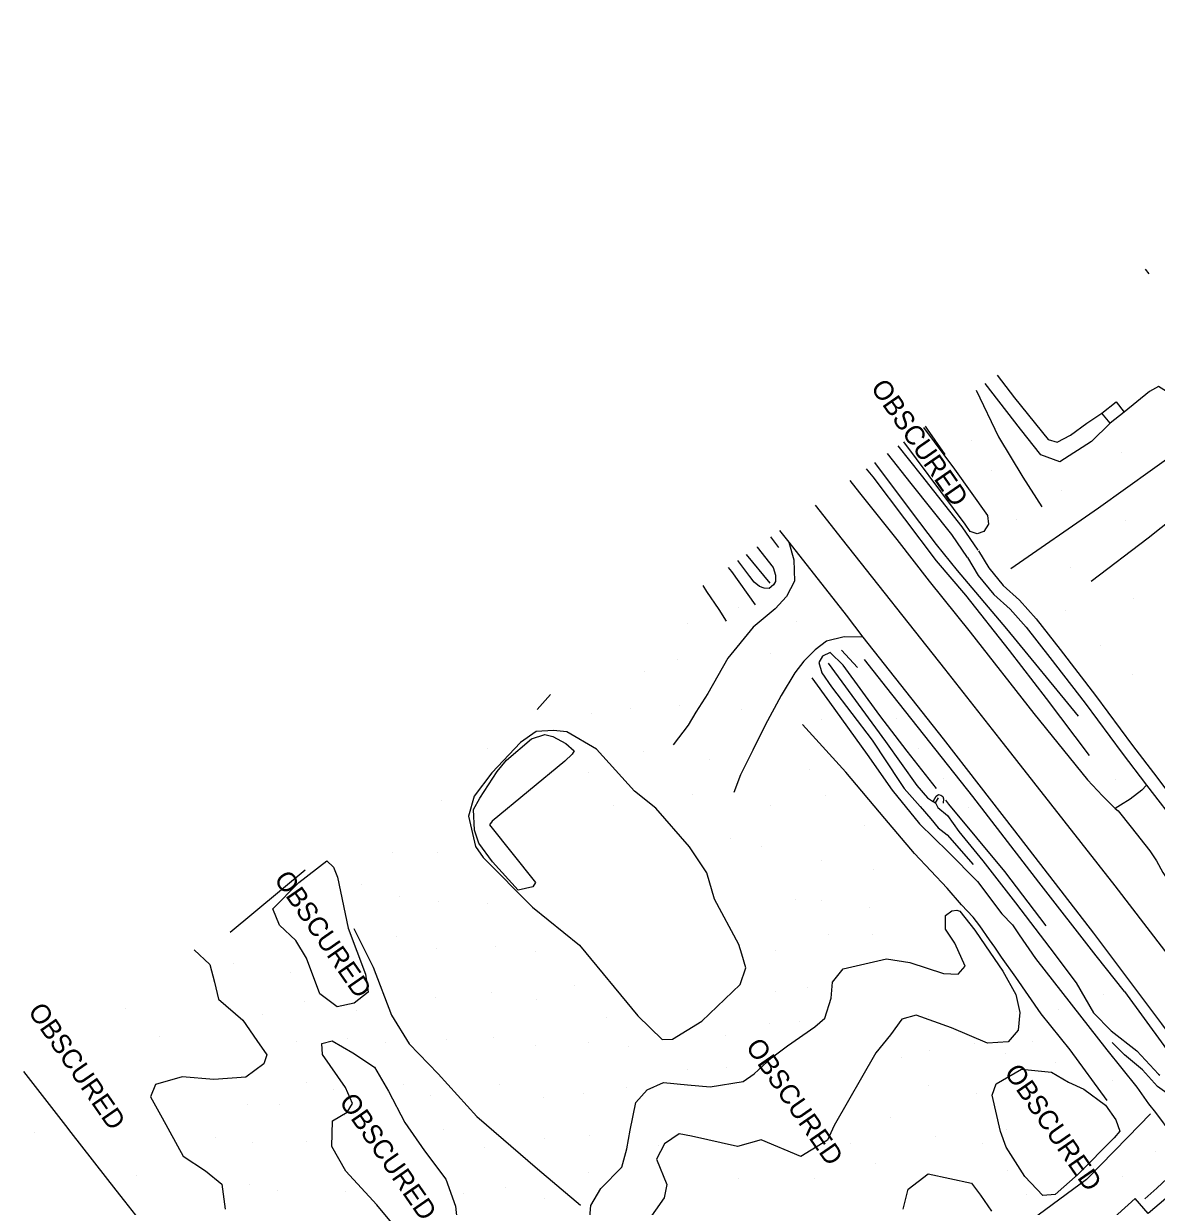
# Model space of a CAD drawing. Extents: x 1497074 to 1501343, y 481943 to 486114.
# Drawn here: x 1497074.4 to 1497425.4, y 484246.4 to 484612.8 of the extents above; entities that cross this region are included whole.
import ezdxf

# ---------------------------------------------------------------- set-up
doc = ezdxf.new("R2010")
doc.units = 0
for name, color, linetype in [('PH Exist DTM Boundary', 7, 'Continuous'), ('PH Exist DTM Breakline', 7, 'Continuous'), ('PH Exist DTM Obscure Area', 7, 'Continuous'), ('PH Exist DTM Obscure Area Text', 7, 'Continuous'), ('PH Exist DTM Point', 7, 'Continuous')]:
    doc.layers.add(name, color=color, linetype=linetype)

msp = doc.modelspace()

# ---------------------------------------------------------------- linework, layer by layer
at = {"layer": 'PH Exist DTM Boundary'}
msp.add_lwpolyline([(1497074.44, 484288.18), (1497081.61, 484278.97), (1497087.44, 484271.49), (1497089.09, 484269.37), (1497103.01, 484251.49), (1497105.67, 484248.08), (1497109.09, 484243.69)], dxfattribs=at)
at = {"layer": 'PH Exist DTM Breakline'}
for points in [[(1497380.31, 484444.03), (1497407.46, 484462.86), (1497432.52, 484480.83), (1497445.3, 484492.35), (1497449.21, 484495.11), (1497452.97, 484497.84), (1497467.42, 484507.84), (1497481.71, 484518.61), (1497492.98, 484526.47), (1497505.2, 484533.04), (1497524.07, 484543.21), (1497536.14, 484549.91), (1497550.63, 484561.75), (1497563.67, 484572.64), (1497570.03, 484578.99), (1497584.26, 484591.02), (1497594.69, 484603.43), (1497601.55, 484612.82)], [(1497438, 484548.3), (1497438.75, 484547.82), (1497448.29, 484535.66), (1497455.84, 484525.45), (1497458.93, 484520.6), (1497459.34, 484517.68), (1497458.41, 484515.46), (1497457.51, 484514.05), (1497455.73, 484512.21), (1497450.73, 484508.04), (1497439.58, 484500.2), (1497433.19, 484496.82), (1497431.49, 484497.08), (1497429.37, 484498.31), (1497426.06, 484500.42), (1497423.32, 484498.86), (1497415.42, 484492.49)], [(1497421.95, 484536.81), (1497423.12, 484535.31)], [(1497376.03, 484503.96), (1497381.48, 484496.95), (1497391.87, 484483.98), (1497394.7, 484483.15), (1497398.75, 484485.34), (1497403.84, 484489.05), (1497408.55, 484492.15)], [(1497369.53, 484499.3), (1497376.5, 484484.83), (1497384.02, 484472.34), (1497389.92, 484463.16)], [(1497411.07, 484489.01), (1497405.35, 484483.38), (1497395.46, 484477.08), (1497389.56, 484479.23), (1497383.26, 484487.24), (1497372.34, 484501.31)], [(1497359.98, 484479.34), (1497354.51, 484487.22), (1497353.89, 484488.12)], [(1497370.19, 484449.68), (1497365.23, 484456.95), (1497352.62, 484472.9), (1497345.4, 484482.04)], [(1497459.96, 484480.9), (1497452.74, 484475.46), (1497443.07, 484468.33), (1497434.38, 484462.64), (1497422.88, 484453.47), (1497405.16, 484440.04)], [(1497338.11, 484476.83), (1497349.44, 484461.65), (1497357.19, 484451.49), (1497363.67, 484443.43)], [(1497366.88, 484447.43), (1497362, 484454.58), (1497349.48, 484470.42), (1497342.14, 484479.71)], [(1497335.46, 484474.93), (1497337.56, 484472.39), (1497357.16, 484446.42), (1497366.26, 484435.81), (1497379.79, 484418.68), (1497391.25, 484403.79), (1497404.56, 484386.16)], [(1497330.44, 484471.34), (1497333.46, 484467.48), (1497345.01, 484453.04), (1497354.97, 484440.14), (1497367.71, 484424.32), (1497387.46, 484399.15), (1497404.03, 484378.57), (1497408.73, 484373.66), (1497412.66, 484369.74), (1497413.55, 484368.93), (1497417.57, 484363.9), (1497423.33, 484356.54), (1497425.41, 484353.48), (1497427.36, 484349.84), (1497429.67, 484346.47), (1497444.52, 484327.11), (1497463.32, 484303.15), (1497468.81, 484296.48), (1497474.96, 484288.97)], [(1497319.69, 484463.65), (1497328.05, 484453.07), (1497359.79, 484412.96), (1497376.84, 484391.29), (1497412.52, 484345.72), (1497442.28, 484307.03), (1497466.31, 484275.69)], [(1497308.67, 484455.76), (1497311.49, 484452.19), (1497329.26, 484429.59), (1497334.45, 484422.8), (1497359.39, 484391.31), (1497381.45, 484362.8), (1497405.91, 484331.07), (1497427.04, 484302.98), (1497436.32, 484290.36), (1497440.65, 484284.44), (1497450.41, 484270.3), (1497454.94, 484263.4), (1497457.72, 484259.47)], [(1497311.49, 484452.19), (1497313.11, 484446.69), (1497313.27, 484440.11), (1497310.79, 484435.32), (1497307.34, 484431.5), (1497300.5, 484425.82), (1497292.63, 484416.24), (1497286.44, 484405.29), (1497282.74, 484399.54), (1497280.31, 484395.55), (1497275.69, 484389.4)], [(1497301.67, 484450.75), (1497301.71, 484450.69), (1497306.66, 484444.35), (1497307.42, 484441.93), (1497307.41, 484440.06), (1497306.79, 484438.95), (1497305.41, 484437.86), (1497303.92, 484437.97), (1497302.45, 484438.42), (1497300.74, 484439.78), (1497299.45, 484441.54), (1497295.71, 484446.49)], [(1497308.41, 484450.52), (1497305.95, 484453.81)], [(1497298.29, 484448.34), (1497305.65, 484439.5)], [(1497366.88, 484447.43), (1497370.22, 484441.91), (1497375.02, 484436.01), (1497380.1, 484431.39), (1497385.1, 484425.83), (1497392.37, 484416.49), (1497403.31, 484402.29), (1497414.81, 484386.8), (1497422.32, 484376.95), (1497432.53, 484363.66), (1497446.51, 484345.69), (1497462.67, 484324.82), (1497475.68, 484307.87), (1497480.66, 484301.39)], [(1497370.34, 484449.52), (1497373.53, 484444.24), (1497377.96, 484438.8), (1497382.96, 484434.25), (1497388.21, 484428.42), (1497395.56, 484418.96), (1497406.54, 484404.72), (1497418.04, 484389.23), (1497425.53, 484379.39), (1497435.95, 484365.36), (1497449.43, 484347.99), (1497465.43, 484326.98), (1497478.45, 484310.03), (1497483.42, 484303.54)], [(1497292.68, 484444.32), (1497293.72, 484443.07), (1497301.14, 484432.81)], [(1497363.67, 484443.43), (1497378.92, 484425.34), (1497401.22, 484398.28)], [(1497292.19, 484427.7), (1497289.98, 484431.31), (1497286.11, 484436.89), (1497284.96, 484438.8)], [(1497334.45, 484422.8), (1497328.72, 484422.86), (1497323.19, 484421.51), (1497319.67, 484418.83), (1497316.15, 484415.31), (1497313.36, 484411.69), (1497309.19, 484404.7), (1497304.2, 484395.47), (1497300.37, 484387.72), (1497296.56, 484380.11), (1497294.45, 484374.6)], [(1497357.32, 484375.84), (1497348.16, 484387.45), (1497339.71, 484398.51), (1497328.35, 484414.13), (1497324.36, 484418.03), (1497321.98, 484416.9), (1497320.81, 484414.94), (1497321.78, 484411.68), (1497324.74, 484407.42), (1497337.3, 484390.81), (1497346.06, 484377.7), (1497347.31, 484375.89), (1497352.26, 484370.26), (1497355.5, 484366.44), (1497357.79, 484363.68), (1497360.56, 484361.49), (1497368.62, 484352.39)], [(1497332.81, 484413.39), (1497327.83, 484418.72)], [(1497323.75, 484414.71), (1497341.44, 484390.4), (1497351.23, 484376.81), (1497354.44, 484373.01), (1497355.76, 484372.13), (1497356.92, 484371.45), (1497357.93, 484373.04)], [(1497415.53, 484312.97), (1497406.7, 484324.01), (1497388.95, 484346.82), (1497368.49, 484373.38), (1497341.91, 484407.02), (1497334.95, 484415.86)], [(1497318.7, 484410.14), (1497324.17, 484402.6), (1497335.82, 484386.46), (1497343.54, 484375.32), (1497351.99, 484364.9), (1497360.88, 484356.29), (1497369.94, 484347.03), (1497377.57, 484337.11), (1497380.78, 484333.64), (1497382.92, 484330.54), (1497387.98, 484323.24), (1497399, 484309.04), (1497410.01, 484294.98), (1497419.33, 484283.35), (1497422.99, 484278.22), (1497425.15, 484275.56), (1497430.19, 484268.72), (1497432.99, 484262.82), (1497431.99, 484258.09), (1497425.55, 484252.06), (1497421.88, 484248.73)], [(1497237.72, 484405), (1497233.59, 484400.32)], [(1497410.21, 484279.26), (1497398.74, 484294.92), (1497389.71, 484306.09), (1497381.84, 484317.41), (1497377.46, 484323.64), (1497375.32, 484326.71), (1497373.71, 484329.02), (1497370.74, 484333.31), (1497368.67, 484336.03), (1497365.07, 484339.87), (1497360.59, 484344.98), (1497350.43, 484355.78), (1497341.26, 484366.56), (1497329.21, 484380.93), (1497315.74, 484395.74)], [(1497216.86, 484354.5), (1497232.08, 484339.16), (1497246.69, 484327.36), (1497264.71, 484305.43), (1497272.29, 484298.14), (1497275.5, 484298.26), (1497284.61, 484303.85), (1497296.49, 484315.21), (1497298.22, 484320.32), (1497297.01, 484324.56), (1497295.99, 484327.53), (1497288.48, 484341.58), (1497286.07, 484349.75), (1497280.79, 484357.86), (1497270.35, 484369.83), (1497263.7, 484375.04), (1497251.98, 484388.12), (1497242.78, 484393.39), (1497238.65, 484393.85), (1497233.26, 484393.53), (1497228.36, 484390.13), (1497219.48, 484380.73), (1497214.04, 484373.47), (1497212.26, 484367.35), (1497214.44, 484357.93), (1497216.86, 484354.5)], [(1497356.38, 484372.07), (1497357.13, 484373.49), (1497357.88, 484374.01), (1497358.65, 484373.86), (1497359.22, 484373.4), (1497359.47, 484372.72), (1497359.31, 484371.34)], [(1497422.32, 484376.95), (1497420.88, 484375.35), (1497417.3, 484372.6), (1497414.29, 484370.76), (1497412.66, 484369.74)], [(1497356.92, 484371.45), (1497357.69, 484369.97), (1497360.64, 484367.48), (1497364.24, 484362.52), (1497371.62, 484353.47), (1497381.8, 484340.49), (1497392.43, 484326.53), (1497400.51, 484315.72), (1497405.89, 484306.36), (1497411.39, 484300.86), (1497419.39, 484294.64), (1497426.06, 484287.43), (1497426.46, 484287.07)], [(1497391.25, 484333.36), (1497378.41, 484350.19), (1497361.14, 484371), (1497360.22, 484372.31)], [(1497161.69, 484350.6), (1497138.38, 484331.23)], [(1497176.75, 484332.53), (1497182.74, 484320.56), (1497188.44, 484305.7), (1497193.91, 484296.77), (1497202.85, 484287.51), (1497214.84, 484274.29), (1497233.69, 484258.05), (1497246.93, 484246.76)], [(1497415.53, 484312.97), (1497427.72, 484296.3), (1497432.27, 484289.74), (1497435.18, 484284.58), (1497438.53, 484278.12), (1497440.28, 484275.19), (1497441.12, 484274.09)], [(1497432.89, 484276.93), (1497430.47, 484280.16), (1497425.74, 484283.58), (1497421.08, 484288.71), (1497415.48, 484293.34), (1497411.72, 484297.19)], [(1497423.6, 484275.1), (1497416.57, 484267.88), (1497403.75, 484254.79), (1497337.98, 484206.23), (1497311.68, 484180.57)], [(1497437.56, 484251.09), (1497434.71, 484254.45), (1497428.34, 484248.9), (1497422.88, 484244.21), (1497418.82, 484248.83), (1497401.66, 484233.36), (1497383.44, 484217.08), (1497360.56, 484196.64), (1497363.2, 484193.52), (1497365.66, 484190.68)]]:
    msp.add_lwpolyline(points, dxfattribs=at)
msp.add_lwpolyline([(1497415.42, 484492.49), (1497411.07, 484489.01), (1497408.55, 484492.15), (1497412.91, 484495.63)], close=True, dxfattribs=at)
at = {"layer": 'PH Exist DTM Obscure Area'}
for points in [[(1497353.29, 484487.69), (1497362.82, 484474.76), (1497373.13, 484460.42), (1497373.36, 484457.74), (1497371.96, 484455.55), (1497369.88, 484454.74), (1497367.73, 484455.46), (1497366.12, 484457.74), (1497362.58, 484462.67)], [(1497362.58, 484462.67), (1497347.16, 484483.3)], [(1497238.45, 484392.02), (1497242.42, 484389.8), (1497245.03, 484387.58), (1497244.4, 484386.52), (1497242.15, 484384.33), (1497219.63, 484365.76), (1497218.77, 484364.63), (1497233.07, 484346.79), (1497232.22, 484345.38), (1497227.71, 484344.44), (1497219.69, 484353.17), (1497215.51, 484358.98), (1497214.1, 484362.99), (1497213.84, 484369.35), (1497215.79, 484372.87), (1497221.14, 484381.18), (1497224.02, 484384.71), (1497231.79, 484391.3), (1497235.94, 484392.64), (1497238.45, 484392.02)], [(1497171.69, 484348.38), (1497174.99, 484332.6), (1497180.35, 484318.37), (1497181.21, 484312.84), (1497176.88, 484309.34), (1497171.58, 484308.25), (1497166.24, 484312.25), (1497162.13, 484323.35), (1497158.75, 484328.85), (1497153.72, 484333.56), (1497151.64, 484338.66), (1497159.74, 484346.78), (1497168.42, 484353.44), (1497170.43, 484351.53), (1497171.69, 484348.38)], [(1497249.15, 484234.83), (1497250.19, 484246.72), (1497253.26, 484251.94), (1497259.75, 484258.62), (1497261.29, 484264.26), (1497262.35, 484270.07), (1497264.14, 484278.6), (1497267.66, 484282.51), (1497272.71, 484284.83), (1497280.13, 484284.08), (1497287.11, 484283.48), (1497297.42, 484285.07), (1497300.83, 484287.54), (1497306.2, 484292.44), (1497311.14, 484296.2), (1497319.56, 484302.01), (1497322.66, 484304.77), (1497324.68, 484310.95), (1497325.09, 484315.94), (1497328.35, 484320.06), (1497341.76, 484323.13), (1497349, 484321.99), (1497359.49, 484318.61), (1497364.02, 484318.39), (1497366.21, 484320.81), (1497362.97, 484327.94), (1497360.12, 484332.35), (1497360.05, 484336.56), (1497362.06, 484337.96), (1497363.61, 484338.22), (1497364.46, 484337.84)], [(1497364.46, 484337.84), (1497369.16, 484331.98), (1497372.51, 484327.11), (1497377.83, 484319.35), (1497381.87, 484312.04), (1497383.12, 484306.46), (1497382.58, 484300.99), (1497379.49, 484297.36), (1497373.1, 484297), (1497361.93, 484301.74), (1497350.98, 484305.66), (1497346.57, 484304.46), (1497343.04, 484299.58), (1497338.47, 484294), (1497325.53, 484271.5), (1497323.51, 484266.94), (1497315.29, 484261.87), (1497302.99, 484267.01), (1497295.61, 484264.98), (1497281.36, 484268.19), (1497277.53, 484268.93), (1497272.97, 484265.77), (1497270.52, 484261.04), (1497273.77, 484253.24), (1497272.86, 484249.1), (1497267.53, 484241.48)], [(1497127.23, 484325.95), (1497132.11, 484321.35), (1497133.56, 484315.9), (1497134.79, 484310.64), (1497142.31, 484304.15), (1497146.7, 484297.84), (1497149.76, 484293.34), (1497148.84, 484290.56), (1497143.26, 484286.44), (1497133.36, 484285.76), (1497123.53, 484286.57), (1497115.26, 484284.22), (1497113.78, 484280.41), (1497117.41, 484273.84), (1497123.9, 484262), (1497130.79, 484257.42), (1497135.89, 484253.35), (1497136.89, 484245.62)], [(1497198.87, 484235.26), (1497188.98, 484240.77), (1497183.88, 484246.95), (1497174.23, 484257.3), (1497169.92, 484264.98), (1497170.1, 484272.92), (1497174.72, 484275.58), (1497176.34, 484278.28), (1497174.16, 484283.29), (1497166.99, 484293.5), (1497166.79, 484296.87), (1497170.07, 484297.71), (1497176.43, 484293.96), (1497183.18, 484289.56), (1497187.53, 484282.09), (1497192.56, 484272.38), (1497198.64, 484263.69), (1497205.23, 484254.84), (1497208.21, 484246.51), (1497209.21, 484237.61), (1497208.02, 484234.48), (1497204.69, 484233.14), (1497201.39, 484234.11), (1497198.87, 484235.26)], [(1497375.72, 484284.4), (1497383.65, 484288.9), (1497392.91, 484287.96), (1497398.17, 484284.91), (1497402.94, 484282.77), (1497409.6, 484277.79), (1497412.85, 484273.28), (1497414.07, 484269.78), (1497412.36, 484267.62), (1497401.19, 484256.37), (1497394.02, 484250.12), (1497390.2, 484249.85), (1497384.67, 484255.7), (1497378.89, 484264.73), (1497377.16, 484269.66), (1497374.56, 484280.89), (1497375.72, 484284.4)], [(1497346.97, 484245.6), (1497348.49, 484251.78), (1497354.74, 484256.49), (1497368.08, 484253.63), (1497370.93, 484249.88), (1497374.28, 484244.93)]]:
    msp.add_lwpolyline(points, dxfattribs=at)
at = {"layer": 'PH Exist DTM Point'}
for p, q in [((1497368.19, 484483.57), (1497368.19, 484483.57)), ((1497414.72, 484480.11), (1497414.72, 484480.11)), ((1497374.42, 484474.45), (1497374.42, 484474.45)), ((1497395.86, 484468.17), (1497395.86, 484468.17)), ((1497382.14, 484459.25), (1497382.14, 484459.25)), ((1497415.85, 484458.84), (1497415.85, 484458.84)), ((1497398.74, 484444.32), (1497398.74, 484444.32)), ((1497418.36, 484434.79), (1497418.36, 484434.79)), ((1497295.88, 484431.93), (1497295.88, 484431.93)), ((1497397.27, 484430.96), (1497397.27, 484430.96)), ((1497280.18, 484427.14), (1497280.18, 484427.14)), ((1497313.99, 484427.57), (1497313.99, 484427.57)), ((1497408.21, 484420.09), (1497408.21, 484420.09)), ((1497277.15, 484415.95), (1497277.15, 484415.95)), ((1497305.93, 484417.59), (1497305.93, 484417.59)), ((1497266.83, 484411.98), (1497266.83, 484411.98)), ((1497417.97, 484411.07), (1497417.97, 484411.07)), ((1497262.35, 484400.57), (1497262.35, 484400.57)), ((1497277.77, 484401.61), (1497277.77, 484401.61)), ((1497296.91, 484400.48), (1497296.91, 484400.48)), ((1497250.25, 484399.22), (1497250.25, 484399.22)), ((1497321.62, 484397.36), (1497321.62, 484397.36)), ((1497344.93, 484397.53), (1497344.93, 484397.53)), ((1497351.82, 484388.43), (1497351.82, 484388.43)), ((1497218.29, 484388.35), (1497218.29, 484388.35)), ((1497266.61, 484387.49), (1497266.61, 484387.49)), ((1497287.08, 484384.88), (1497287.08, 484384.88)), ((1497317.9, 484381.62), (1497317.9, 484381.62)), ((1497249.42, 484380.92), (1497249.42, 484380.92)), ((1497359.51, 484378.85), (1497359.51, 484378.85)), ((1497412.7, 484378.56), (1497412.7, 484378.56)), ((1497281.67, 484373.93), (1497281.67, 484373.93)), ((1497322.91, 484373.86), (1497322.91, 484373.86)), ((1497203.79, 484372.04), (1497203.79, 484372.04)), ((1497257.07, 484370.55), (1497257.07, 484370.55)), ((1497305.92, 484370.63), (1497305.92, 484370.63)), ((1497367.11, 484370.04), (1497367.11, 484370.04)), ((1497334.95, 484364.3), (1497334.95, 484364.3)), ((1497293.51, 484360.27), (1497293.51, 484360.27)), ((1497188.65, 484356.07), (1497188.65, 484356.07)), ((1497202.65, 484356.01), (1497202.65, 484356.01)), ((1497302.97, 484357.86), (1497302.97, 484357.86)), ((1497321.69, 484353.53), (1497321.69, 484353.53)), ((1497337.63, 484350.92), (1497337.63, 484350.92)), ((1497179.06, 484346.05), (1497179.06, 484346.05)), ((1497190.91, 484342.34), (1497190.91, 484342.34)), ((1497313.68, 484341.6), (1497313.68, 484341.6)), ((1497321.68, 484341.28), (1497321.68, 484341.28)), ((1497203.05, 484340.74), (1497203.05, 484340.74)), ((1497218.15, 484340.23), (1497218.15, 484340.23)), ((1497336.62, 484339.05), (1497336.62, 484339.05)), ((1497190.01, 484329.94), (1497190.01, 484329.94)), ((1497323.76, 484330.75), (1497323.76, 484330.75)), ((1497337.48, 484330.74), (1497337.48, 484330.74)), ((1497202.39, 484326.45), (1497202.39, 484326.45)), ((1497220.53, 484326.83), (1497220.53, 484326.83)), ((1497233.13, 484325.53), (1497233.13, 484325.53)), ((1497307.37, 484325.65), (1497307.37, 484325.65)), ((1497139.52, 484321.75), (1497139.52, 484321.75)), ((1497157.15, 484318.9), (1497157.15, 484318.9)), ((1497219.36, 484312.77), (1497219.36, 484312.77)), ((1497245.21, 484314.78), (1497245.21, 484314.78)), ((1497307.4, 484312.91), (1497307.4, 484312.91)), ((1497317.26, 484314.28), (1497317.26, 484314.28)), ((1497409, 484312.16), (1497409, 484312.16)), ((1497161.42, 484309.83), (1497161.42, 484309.83)), ((1497202.14, 484310.99), (1497202.14, 484310.99)), ((1497233.43, 484310.48), (1497233.43, 484310.48)), ((1497106.12, 484307.7), (1497106.12, 484307.7)), ((1497148.42, 484305.99), (1497148.42, 484305.99)), ((1497177.52, 484307.2), (1497177.52, 484307.2)), ((1497254.97, 484305.09), (1497254.97, 484305.09)), ((1497354.89, 484305.21), (1497354.89, 484305.21)), ((1497381.93, 484306.7), (1497381.93, 484306.7)), ((1497395.03, 484307.31), (1497395.03, 484307.31)), ((1497305.46, 484303.04), (1497305.46, 484303.04)), ((1497314.94, 484303.85), (1497314.94, 484303.85)), ((1497116.4, 484299.06), (1497116.4, 484299.06)), ((1497158.86, 484297.39), (1497158.86, 484297.39)), ((1497174.92, 484298.38), (1497174.92, 484298.38)), ((1497186.47, 484297.05), (1497186.47, 484297.05)), ((1497205.36, 484298.03), (1497205.36, 484298.03)), ((1497219.95, 484298.61), (1497219.95, 484298.61)), ((1497249.52, 484297.13), (1497249.52, 484297.13)), ((1497291.8, 484299.36), (1497291.8, 484299.36)), ((1497369.19, 484297), (1497369.19, 484297)), ((1497386.96, 484297.54), (1497386.96, 484297.54)), ((1497233.16, 484296.22), (1497233.16, 484296.22)), ((1497261.99, 484296.04), (1497261.99, 484296.04)), ((1497355.24, 484294.66), (1497355.24, 484294.66)), ((1497378.71, 484293.68), (1497378.71, 484293.68)), ((1497292.19, 484289.59), (1497292.19, 484289.59)), ((1497346.49, 484292.6), (1497346.49, 484292.6)), ((1497394.25, 484290.88), (1497394.25, 484290.88)), ((1497280.06, 484288.7), (1497280.06, 484288.7)), ((1497161.94, 484284.71), (1497161.94, 484284.71)), ((1497170.57, 484282.69), (1497170.57, 484282.69)), ((1497192.17, 484284.23), (1497192.17, 484284.23)), ((1497221.96, 484284.25), (1497221.96, 484284.25)), ((1497261.29, 484283.36), (1497261.29, 484283.36)), ((1497354.85, 484283.93), (1497354.85, 484283.93)), ((1497411.92, 484285.48), (1497411.92, 484285.48)), ((1497200.63, 484280.89), (1497200.63, 484280.89)), ((1497235.59, 484280.16), (1497235.59, 484280.16)), ((1497248.05, 484281.45), (1497248.05, 484281.45)), ((1497369.67, 484281.25), (1497369.67, 484281.25)), ((1497143.72, 484278.03), (1497143.72, 484278.03)), ((1497153.75, 484277.86), (1497153.75, 484277.86)), ((1497173.97, 484274.66), (1497173.97, 484274.66)), ((1497343.13, 484273.82), (1497343.13, 484273.82)), ((1497077.9, 484269.28), (1497077.9, 484269.28)), ((1497133.73, 484267.71), (1497133.73, 484267.71)), ((1497204.68, 484270.15), (1497204.68, 484270.15)), ((1497249.67, 484268.29), (1497249.67, 484268.29)), ((1497262.08, 484269.58), (1497262.08, 484269.58)), ((1497357.09, 484268.22), (1497357.09, 484268.22)), ((1497379.07, 484270.38), (1497379.07, 484270.38)), ((1497145.38, 484266.37), (1497145.38, 484266.37)), ((1497162.14, 484266.67), (1497162.14, 484266.67)), ((1497217.23, 484264.55), (1497217.23, 484264.55)), ((1497235.81, 484267.41), (1497235.81, 484267.41)), ((1497271.25, 484265.34), (1497271.25, 484265.34)), ((1497330.55, 484266.01), (1497330.55, 484266.01)), ((1497371.56, 484265.77), (1497371.56, 484265.77)), ((1497425.08, 484263.44), (1497425.08, 484263.44)), ((1497249.58, 484256.87), (1497249.58, 484256.87)), ((1497259.3, 484258.62), (1497259.3, 484258.62)), ((1497338.3, 484259.83), (1497338.3, 484259.83)), ((1497379.3, 484257.55), (1497379.3, 484257.55)), ((1497109.41, 484255.93), (1497109.41, 484255.93)), ((1497144.38, 484253.14), (1497144.38, 484253.14)), ((1497296.07, 484254.94), (1497296.07, 484254.94)), ((1497319.48, 484255), (1497319.48, 484255)), ((1497414.98, 484255.59), (1497414.98, 484255.59)), ((1497153, 484251.48), (1497153, 484251.48)), ((1497174.05, 484250.95), (1497174.05, 484250.95)), ((1497210.84, 484250.55), (1497210.84, 484250.55)), ((1497223.59, 484252.15), (1497223.59, 484252.15)), ((1497385.18, 484250.08), (1497385.18, 484250.08)), ((1497235.91, 484248.98), (1497235.91, 484248.98))]:
    msp.add_line(p, q, dxfattribs=at)

# ---------------------------------------------------------------- texts
at = {"layer": 'PH Exist DTM Obscure Area Text'}
for p in [(1497336.7, 484500.05), (1497151.83, 484347.8), (1497075.59, 484306.87), (1497297.96, 484295.9), (1497378.09, 484287.93), (1497172, 484278.87)]:
    msp.add_text('OBSCURED', height=6, rotation=304.7435, dxfattribs=at).set_placement(p)

doc.saveas('drawing.dxf')
